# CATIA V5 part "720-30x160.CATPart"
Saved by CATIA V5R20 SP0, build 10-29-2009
Part number: 720-30x160
Definition: NONE
Nomenclature: 720-30x160
Source: Unknown
Description: 720-30x160
Bounding box of the stored display mesh (mm): x 0 to 160, y -15 to 15, z -15 to 15
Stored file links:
  C:\Users\Utente\Desktop\IO LAVORO\3D X SITO CF\X SITO\720\720-30x160.CATPart
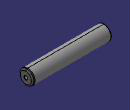
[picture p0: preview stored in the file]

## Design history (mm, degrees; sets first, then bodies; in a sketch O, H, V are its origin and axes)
Body1 "720-30x160" (main body)
  Solid1: solid without history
